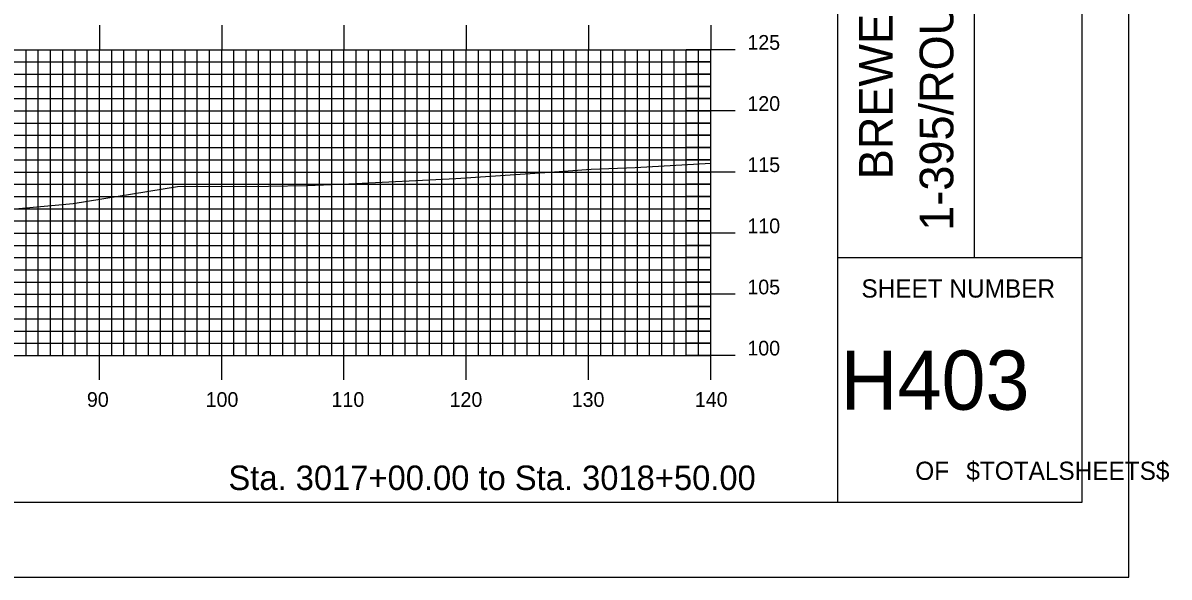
# Model space of a CAD drawing. Extents: x 1685586 to 1685929, y 461260 to 461480.
# Drawn here: x 1685835.5 to 1685929.2, y 461260 to 461305.3 of the extents above; entities that cross this region are included whole.
import ezdxf

# ---------------------------------------------------------------- set-up
doc = ezdxf.new("R2010")
doc.units = 0
for name, color, linetype in [('BORDER', 7, 'Continuous'), ('H_V ANNOTATION', 7, 'Continuous'), ('MAJOR', 7, 'Continuous'), ('MINOR', 7, 'Continuous'), ('PLOT BOUNDARY', 7, 'Continuous'), ('S_Roadway_Centerline', 7, 'Continuous')]:
    doc.layers.add(name, color=color, linetype=linetype)

msp = doc.modelspace()

# ---------------------------------------------------------------- linework, layer by layer
at = {"layer": 'BORDER'}
for p, q in [((1685902.142, 461266.072), (1685902.142, 461476.072)), ((1685913.325, 461286.078), (1685913.325, 461356.078)), ((1685902.142, 461286.078), (1685922.142, 461286.078))]:
    msp.add_line(p, q, dxfattribs=at)
msp.add_lwpolyline([(1685602.142, 461266.072), (1685922.142, 461266.072), (1685922.142, 461476.072), (1685602.142, 461476.072)], close=True, dxfattribs=at)
at = {"layer": 'MAJOR'}
for p, q in [((1685841.742, 461305.076), (1685841.742, 461303.072)), ((1685851.742, 461305.076), (1685851.742, 461303.072)), ((1685861.742, 461305.076), (1685861.742, 461303.072)), ((1685871.742, 461305.076), (1685871.742, 461303.072)), ((1685881.742, 461305.076), (1685881.742, 461303.072)), ((1685891.742, 461305.076), (1685891.742, 461303.072)), ((1685611.742, 461303.072), (1685891.742, 461303.072)), ((1685611.742, 461303.072), (1685891.742, 461303.072)), ((1685841.742, 461278.072), (1685841.742, 461303.072)), ((1685851.742, 461278.072), (1685851.742, 461303.072)), ((1685861.742, 461278.072), (1685861.742, 461303.072)), ((1685871.742, 461278.072), (1685871.742, 461303.072)), ((1685881.742, 461278.072), (1685881.742, 461303.072)), ((1685893.746, 461303.072), (1685889.738, 461303.072)), ((1685891.742, 461278.072), (1685891.742, 461303.072)), ((1685891.742, 461278.072), (1685891.742, 461303.072)), ((1685611.742, 461298.072), (1685891.742, 461298.072)), ((1685893.746, 461298.072), (1685889.738, 461298.072)), ((1685611.742, 461293.072), (1685891.742, 461293.072)), ((1685893.746, 461293.072), (1685889.738, 461293.072)), ((1685611.742, 461288.072), (1685891.742, 461288.072)), ((1685893.746, 461288.072), (1685889.738, 461288.072)), ((1685611.742, 461283.072), (1685891.742, 461283.072)), ((1685893.746, 461283.072), (1685889.738, 461283.072)), ((1685611.742, 461278.072), (1685891.742, 461278.072)), ((1685611.742, 461278.072), (1685891.742, 461278.072)), ((1685841.742, 461276.068), (1685841.742, 461278.072)), ((1685851.742, 461276.068), (1685851.742, 461278.072)), ((1685861.742, 461276.068), (1685861.742, 461278.072)), ((1685871.742, 461276.068), (1685871.742, 461278.072)), ((1685881.742, 461276.068), (1685881.742, 461278.072)), ((1685893.746, 461278.072), (1685889.738, 461278.072)), ((1685891.742, 461276.068), (1685891.742, 461278.072))]:
    msp.add_line(p, q, dxfattribs=at)
at = {"layer": 'MINOR'}
for p, q in [((1685835.742, 461278.072), (1685835.742, 461303.072)), ((1685836.742, 461278.072), (1685836.742, 461303.072)), ((1685837.742, 461278.072), (1685837.742, 461303.072)), ((1685838.742, 461278.072), (1685838.742, 461303.072)), ((1685839.742, 461278.072), (1685839.742, 461303.072)), ((1685840.742, 461278.072), (1685840.742, 461303.072)), ((1685842.742, 461278.072), (1685842.742, 461303.072)), ((1685843.742, 461278.072), (1685843.742, 461303.072)), ((1685844.742, 461278.072), (1685844.742, 461303.072)), ((1685845.742, 461278.072), (1685845.742, 461303.072)), ((1685846.742, 461278.072), (1685846.742, 461303.072)), ((1685847.742, 461278.072), (1685847.742, 461303.072)), ((1685848.742, 461278.072), (1685848.742, 461303.072)), ((1685849.742, 461278.072), (1685849.742, 461303.072)), ((1685850.742, 461278.072), (1685850.742, 461303.072)), ((1685852.742, 461278.072), (1685852.742, 461303.072)), ((1685853.742, 461278.072), (1685853.742, 461303.072)), ((1685854.742, 461278.072), (1685854.742, 461303.072)), ((1685855.742, 461278.072), (1685855.742, 461303.072)), ((1685856.742, 461278.072), (1685856.742, 461303.072)), ((1685857.742, 461278.072), (1685857.742, 461303.072)), ((1685858.742, 461278.072), (1685858.742, 461303.072)), ((1685859.742, 461278.072), (1685859.742, 461303.072)), ((1685860.742, 461278.072), (1685860.742, 461303.072)), ((1685862.742, 461278.072), (1685862.742, 461303.072)), ((1685863.742, 461278.072), (1685863.742, 461303.072)), ((1685864.742, 461278.072), (1685864.742, 461303.072)), ((1685865.742, 461278.072), (1685865.742, 461303.072)), ((1685866.742, 461278.072), (1685866.742, 461303.072)), ((1685867.742, 461278.072), (1685867.742, 461303.072)), ((1685868.742, 461278.072), (1685868.742, 461303.072)), ((1685869.742, 461278.072), (1685869.742, 461303.072)), ((1685870.742, 461278.072), (1685870.742, 461303.072)), ((1685872.742, 461278.072), (1685872.742, 461303.072)), ((1685873.742, 461278.072), (1685873.742, 461303.072)), ((1685874.742, 461278.072), (1685874.742, 461303.072)), ((1685875.742, 461278.072), (1685875.742, 461303.072)), ((1685876.742, 461278.072), (1685876.742, 461303.072)), ((1685877.742, 461278.072), (1685877.742, 461303.072)), ((1685878.742, 461278.072), (1685878.742, 461303.072)), ((1685879.742, 461278.072), (1685879.742, 461303.072)), ((1685880.742, 461278.072), (1685880.742, 461303.072)), ((1685882.742, 461278.072), (1685882.742, 461303.072)), ((1685883.742, 461278.072), (1685883.742, 461303.072)), ((1685884.742, 461278.072), (1685884.742, 461303.072)), ((1685885.742, 461278.072), (1685885.742, 461303.072)), ((1685886.742, 461278.072), (1685886.742, 461303.072)), ((1685887.742, 461278.072), (1685887.742, 461303.072)), ((1685888.742, 461278.072), (1685888.742, 461303.072)), ((1685889.742, 461278.072), (1685889.742, 461303.072)), ((1685890.742, 461278.072), (1685890.742, 461303.072)), ((1685611.742, 461302.072), (1685891.742, 461302.072)), ((1685891.742, 461302.072), (1685889.738, 461302.072)), ((1685611.742, 461301.072), (1685891.742, 461301.072)), ((1685891.742, 461301.072), (1685889.738, 461301.072)), ((1685611.742, 461300.072), (1685891.742, 461300.072)), ((1685891.742, 461300.072), (1685889.738, 461300.072)), ((1685611.742, 461299.072), (1685891.742, 461299.072)), ((1685891.742, 461299.072), (1685889.738, 461299.072)), ((1685611.742, 461297.072), (1685891.742, 461297.072)), ((1685891.742, 461297.072), (1685889.738, 461297.072)), ((1685611.742, 461296.072), (1685891.742, 461296.072)), ((1685891.742, 461296.072), (1685889.738, 461296.072)), ((1685611.742, 461295.072), (1685891.742, 461295.072)), ((1685891.742, 461295.072), (1685889.738, 461295.072)), ((1685611.742, 461294.072), (1685891.742, 461294.072)), ((1685891.742, 461294.072), (1685889.738, 461294.072)), ((1685611.742, 461292.072), (1685891.742, 461292.072)), ((1685891.742, 461292.072), (1685889.738, 461292.072)), ((1685611.742, 461291.072), (1685891.742, 461291.072)), ((1685891.742, 461291.072), (1685889.738, 461291.072)), ((1685611.742, 461290.072), (1685891.742, 461290.072)), ((1685891.742, 461290.072), (1685889.738, 461290.072)), ((1685611.742, 461289.072), (1685891.742, 461289.072)), ((1685891.742, 461289.072), (1685889.738, 461289.072)), ((1685611.742, 461287.072), (1685891.742, 461287.072)), ((1685891.742, 461287.072), (1685889.738, 461287.072)), ((1685611.742, 461286.072), (1685891.742, 461286.072)), ((1685891.742, 461286.072), (1685889.738, 461286.072)), ((1685611.742, 461285.072), (1685891.742, 461285.072)), ((1685891.742, 461285.072), (1685889.738, 461285.072)), ((1685611.742, 461284.072), (1685891.742, 461284.072)), ((1685891.742, 461284.072), (1685889.738, 461284.072)), ((1685611.742, 461282.072), (1685891.742, 461282.072)), ((1685891.742, 461282.072), (1685889.738, 461282.072)), ((1685611.742, 461281.072), (1685891.742, 461281.072)), ((1685891.742, 461281.072), (1685889.738, 461281.072)), ((1685611.742, 461280.072), (1685891.742, 461280.072)), ((1685891.742, 461280.072), (1685889.738, 461280.072)), ((1685611.742, 461279.072), (1685891.742, 461279.072)), ((1685891.742, 461279.072), (1685889.738, 461279.072))]:
    msp.add_line(p, q, dxfattribs=at)
at = {"layer": 'PLOT BOUNDARY'}
msp.add_lwpolyline([(1685585.956, 461259.954), (1685925.956, 461259.954), (1685925.956, 461479.954), (1685585.956, 461479.954)], close=True, dxfattribs=at)
at = {"layer": 'S_Roadway_Centerline'}
msp.add_lwpolyline([(1685835.16, 461290.09), (1685839.59, 461290.492), (1685848.137, 461291.886), (1685855.574, 461291.917), (1685858.7, 461291.977), (1685862.136, 461292.114), (1685870.885, 461292.537), (1685878.595, 461293.056), (1685881.957, 461293.306), (1685885.564, 461293.434), (1685891.742, 461293.798)], dxfattribs=at)

# ---------------------------------------------------------------- texts
at = {"layer": 'BORDER'}
for s, p in [('1-395/ROUTE 9 CONNECTOR', (1685911.592, 461288.272)), ('BREWER TO EDDINGTON', (1685906.631, 461292.481))]:
    msp.add_text(s, height=2.75575, rotation=90, dxfattribs=at).set_placement(p)
for s, height, p in [('SHEET NUMBER', 1.49054, (1685904.073, 461282.805)), ('H403', 4.8388, (1685902.353, 461273.637)), ('OF', 1.4905, (1685908.476, 461267.898)), ('$TOTALSHEETS$', 1.49054, (1685912.655, 461267.898))]:
    msp.add_text(s, height=height, dxfattribs=at).set_placement(p)
at = {"layer": 'H_V ANNOTATION'}
for s, height, p in [('125', 1.2, (1685894.742, 461303.072)), ('120', 1.2, (1685894.742, 461298.072)), ('115', 1.2, (1685894.742, 461293.072)), ('110', 1.2, (1685894.742, 461288.072)), ('105', 1.2, (1685894.742, 461283.072)), ('100', 1.2, (1685894.742, 461278.072)), ('90', 1.2, (1685840.715, 461273.872)), ('100', 1.2, (1685850.426, 461273.872)), ('110', 1.2, (1685860.726, 461273.872)), ('120', 1.2, (1685870.383, 461273.872)), ('130', 1.2, (1685880.372, 461273.872)), ('140', 1.2, (1685890.447, 461273.872)), ('Sta. 3017+00.00 to Sta. 3018+50.00', 2.0004, (1685852.295, 461267.072))]:
    msp.add_text(s, height=height, dxfattribs=at).set_placement(p)

doc.saveas('drawing.dxf')
